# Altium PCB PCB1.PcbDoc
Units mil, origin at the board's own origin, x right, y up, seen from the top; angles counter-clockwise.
Board outline 2300 x 3730 mil, 2 copper layers (Top Layer, Bottom Layer); 8 components, 16 nets, 83 pads, 4 vias.
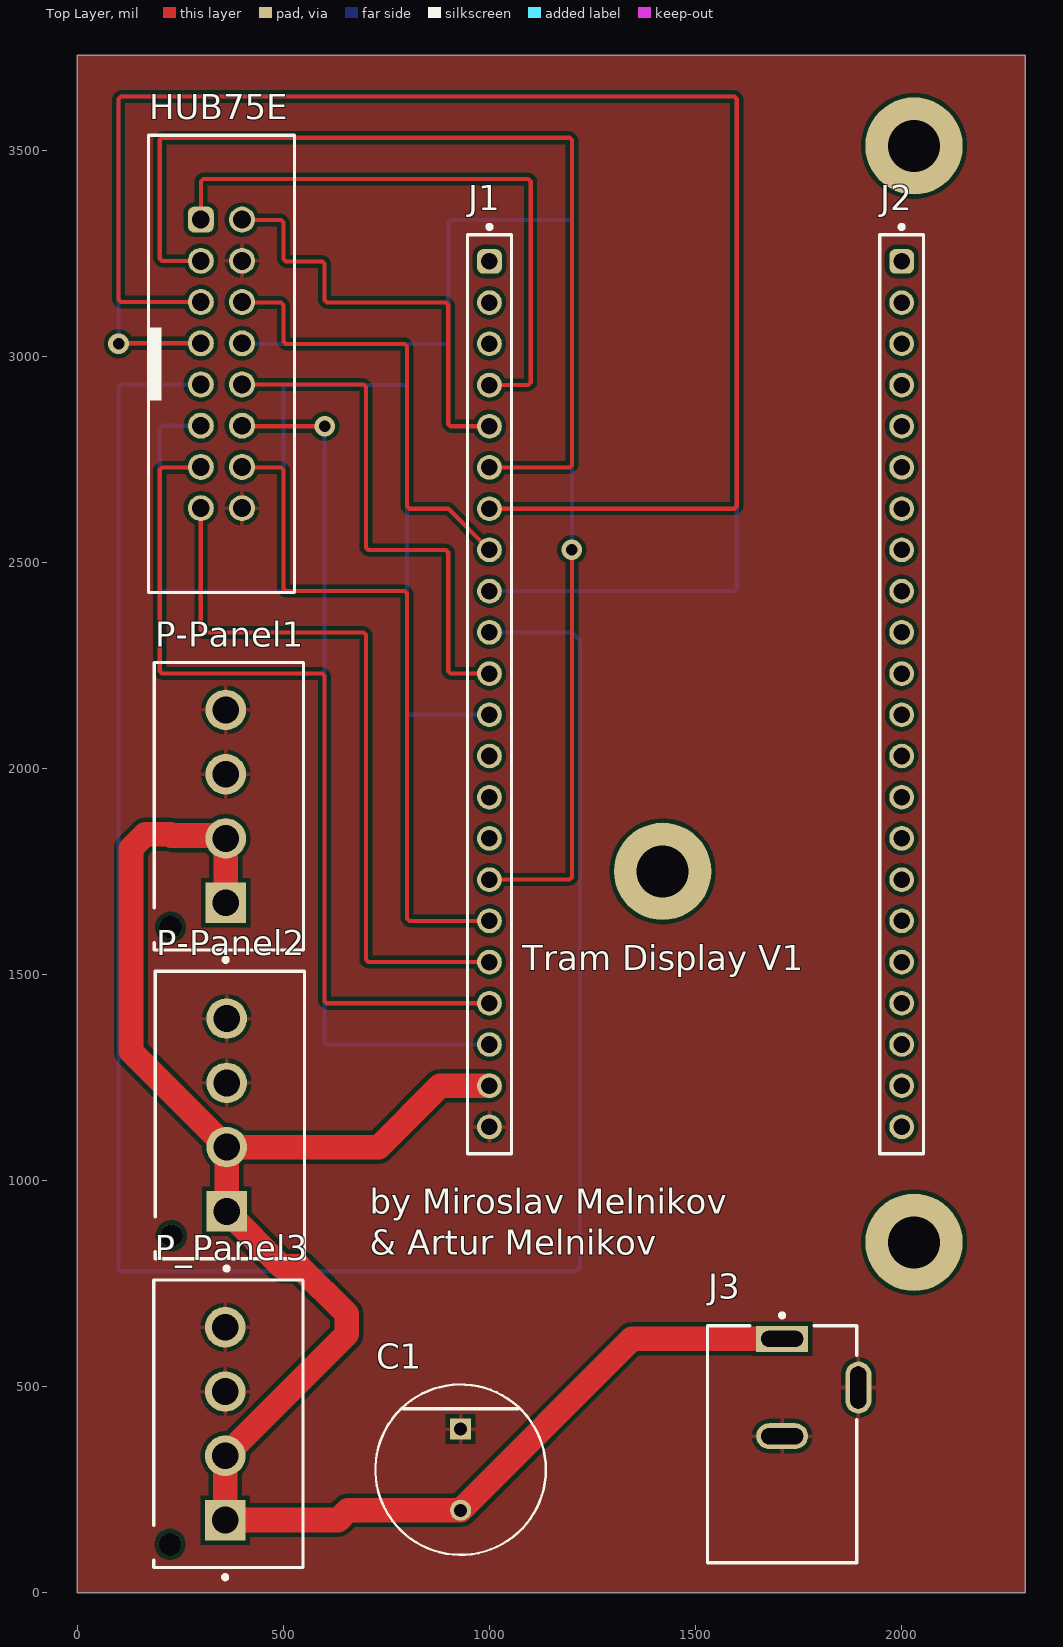
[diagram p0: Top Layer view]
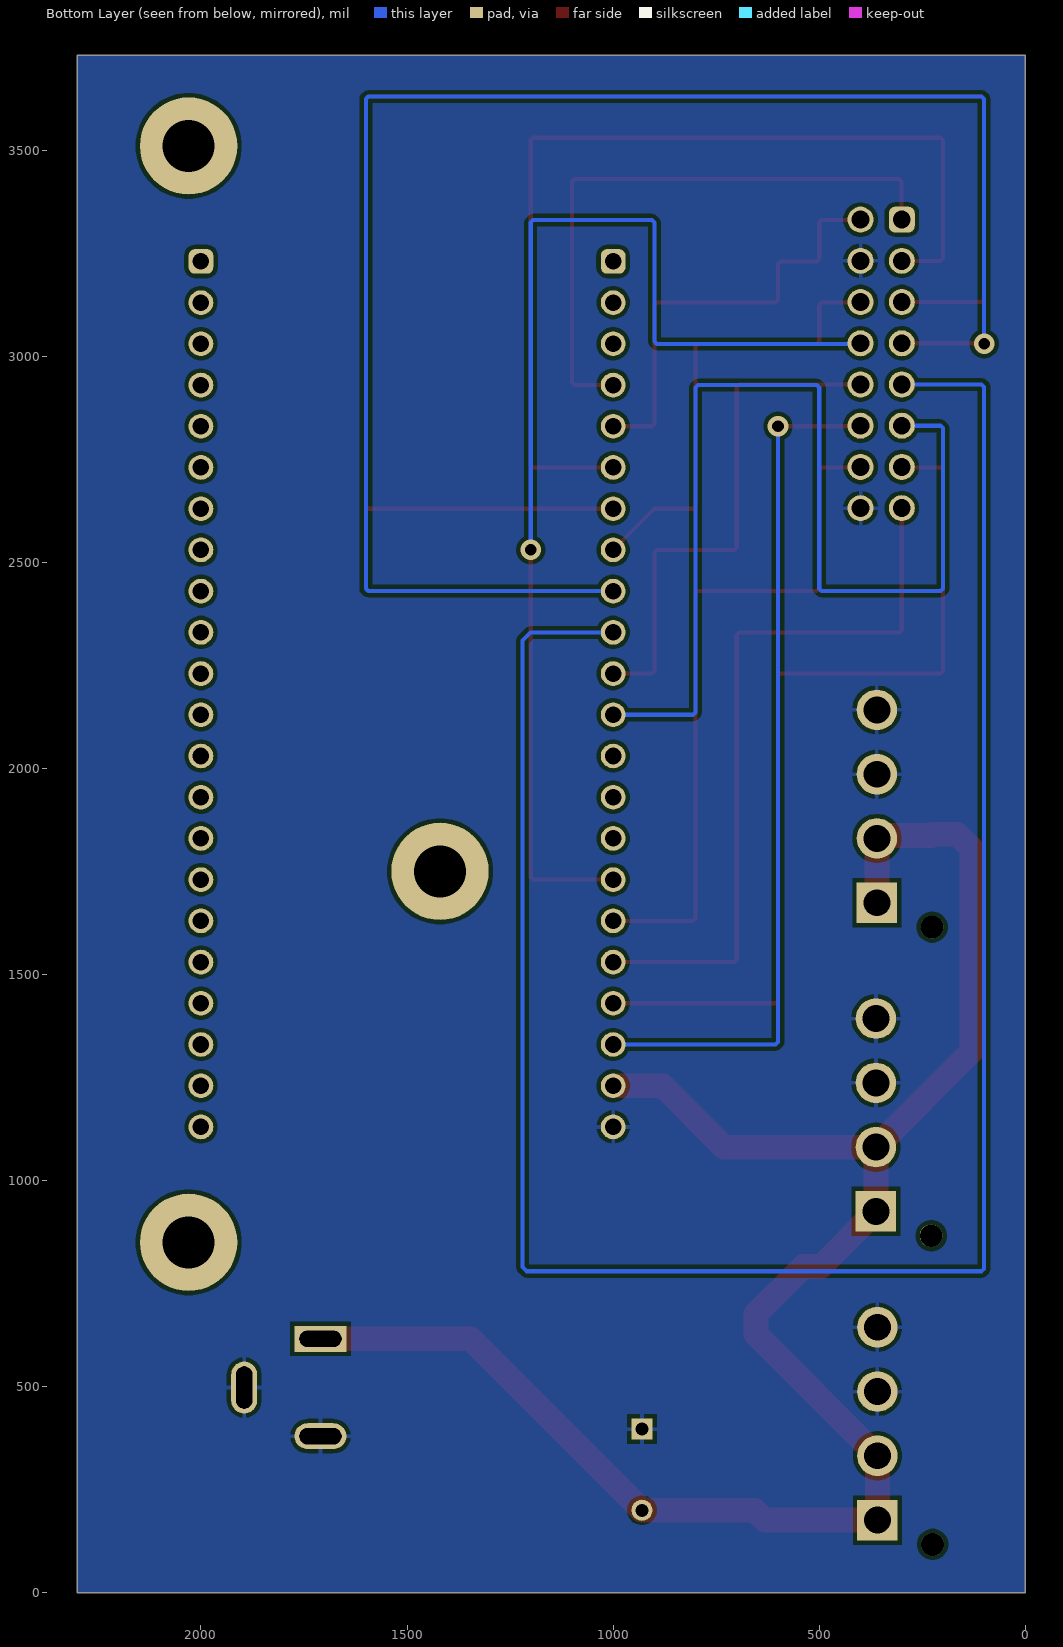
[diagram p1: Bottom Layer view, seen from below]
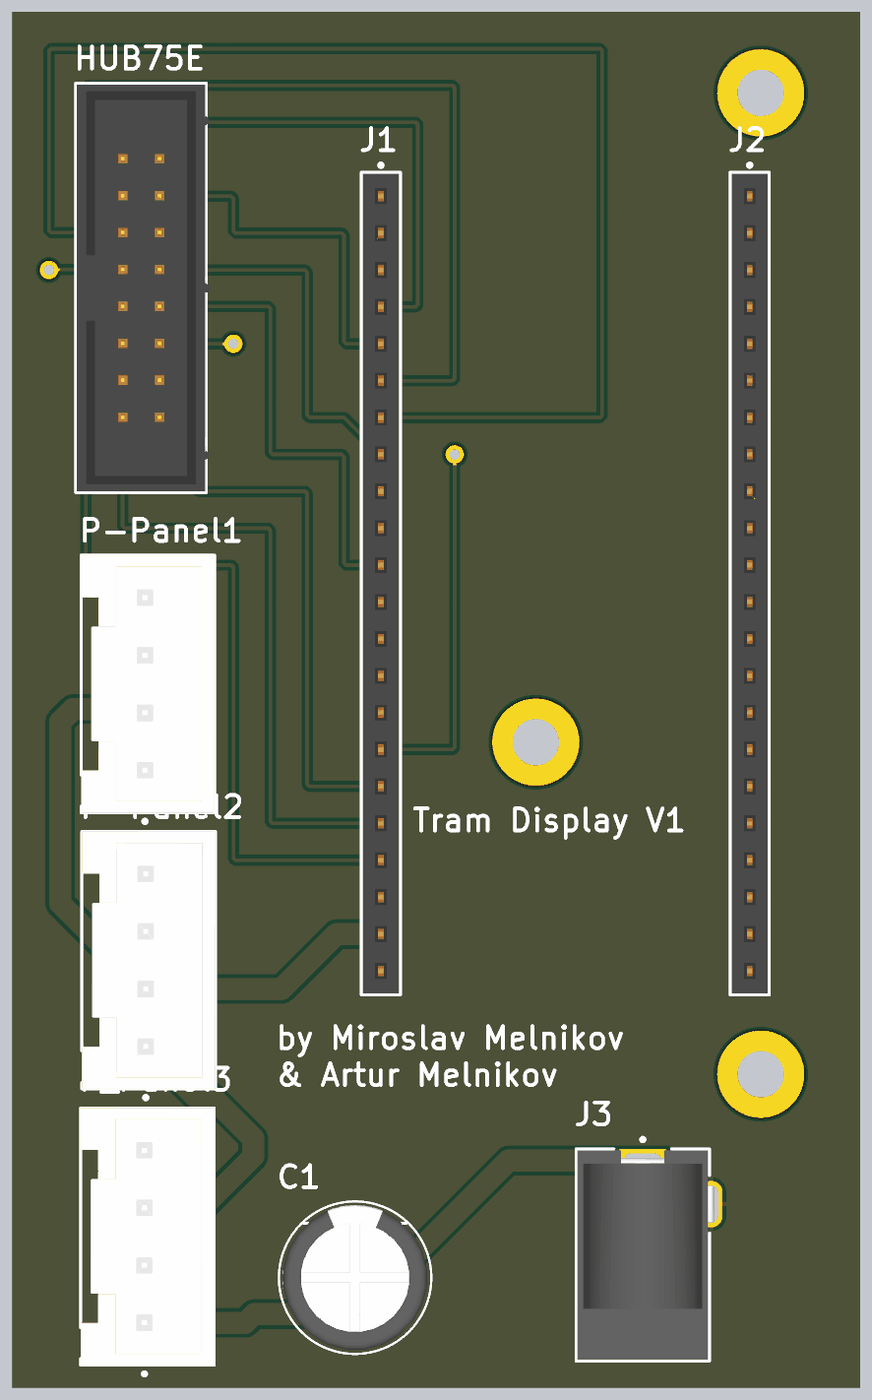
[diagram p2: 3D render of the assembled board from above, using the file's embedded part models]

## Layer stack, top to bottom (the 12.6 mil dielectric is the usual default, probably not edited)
Top Solder: solder mask 0.4, Solder Resist, Dk 3.5
Top Layer: signal copper 1.4
Dielectric 1: dielectric 12.6, FR-4, Dk 4.8
Bottom Layer: signal copper 1.4
Bottom Solder: solder mask 0.4, Solder Resist, Dk 3.5

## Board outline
0,0 2300,0 2300,3730 0,3730

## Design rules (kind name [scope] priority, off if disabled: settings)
AssemblyTestpoint [All] p1: testpointundercomponent=TRUE minsize=40 maxsize=100 preferedsize=60 minholesize=0 maxholesize=40 preferedholesize=32 testpointgrid=1 usegrid=TRUE gridoriginx=900 gridoriginy=1370 gridtolerance=0.01 allowsidetop=TRUE allowsidebottom=TRUE
Clearance [All] p1: gap=10 ignorepadtopadclearanceinfootprint=FALSE
FabricationTestpoint [All] p1: side=3 testpointundercomponent=TRUE minsize=40 maxsize=100 preferedsize=60 minholesize=0 maxholesize=40 preferedholesize=32 testpointgrid=1 allowsidetop=TRUE allowsidebottom=TRUE usegrid=TRUE gridoriginx=900 gridoriginy=1370 gridtolerance=0.01
PolygonConnect [All] p1: connectstyle=Relief reliefconductorwidth=10 reliefentries=4 polygonreliefangle="90 Angle" airgapwidth=10
RoutingVias [All] p1: holewidth=28 width=50 viastyle="Through Hole" minholewidth=28 minwidth=50 maxholewidth=28 maxwidth=50
SolderMaskExpansion [All] p1: expansion=4 istentingtop=FALSE
SupplyNets "Schematic Supply Nets" [InNet('GND')] p1: voltage=0.000
Width Power_Width [InNet('5Vin')] p1: maxlimit=120 minlimit=20 preferedwidth=60 minimp=50.000000 maximp=50.000000 favimp=50.000000
Width [All] p2: maxlimit=10 minlimit=10 preferedwidth=10
28 further rules are at their usual default settings.

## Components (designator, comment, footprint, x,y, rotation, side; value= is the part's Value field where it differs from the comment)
C1 "EEUTA1A102" FP-RAD-TH-D_10_0_5-L_20_2-MFG 930,298.43 r270 top
HUB75E "61201621621" 61201621621 349.63,2981.34 r270 top
J1 "61302211821" 61302211821 1000,2180 r270 top
J2 "61302211821" 61302211821 2000,2180 r270 top
J3 "PJ-102A" FP-PJ-102A-MFG 1710,360 r180 top
P-Panel1 "BH4P-VH-1(LF)(SN)" FP-BH4P-VH-1_LF_SN-MFG 367.87,1907.95 r90 top
P-Panel2 "BH4P-VH-1(LF)(SN)" FP-BH4P-VH-1_LF_SN-MFG 370.19,1158.98 r90 top
P_Panel3 "BH4P-VH-1(LF)(SN)" FP-BH4P-VH-1_LF_SN-MFG 366.63,410 r90 top

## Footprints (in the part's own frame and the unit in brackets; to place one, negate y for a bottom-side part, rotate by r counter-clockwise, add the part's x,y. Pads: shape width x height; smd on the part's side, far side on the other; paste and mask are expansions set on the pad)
61201621621 [mm] "16 pins, straight, gold plating"
  rrect50% 1.6x1.6 hole 1.1: 1(-8.89,-1.27)
  round 1.6 hole 1.1: 2(-8.89,1.27) 3(-6.35,-1.27) 4(-6.35,1.27) 5(-3.81,-1.27) 6(-3.81,1.27) 7(-1.27,-1.27) 8(-1.27,1.27) 9(1.27,-1.27) 10(1.27,1.27) 11(3.81,-1.27) 12(3.81,1.27) 13(6.35,-1.27) 14(6.35,1.27) 15(8.89,-1.27) 16(8.89,1.27)
  silkscreen extent -14.09,-4.5 14.09,4.5, body extent -13.99,-4.42 13.99,4.75, height 9.13
61302211821 [mm] "Socket Header, Pitch 2.54 mm, THT, Vertical, single row, 22p"
  rrect50% 1.52x1.52 hole 1.02: 1(-26.67,0)
  round 1.52 hole 1.02: 2(-24.13,0) 3(-21.59,0) 4(-19.05,0) 5(-16.51,0) 6(-13.97,0) 7(-11.43,0) 8(-8.89,0) 9(-6.35,0) 10(-3.81,0) 11(-1.27,0) 12(1.27,0) 13(3.81,0) 14(6.35,0) 15(8.89,0) 16(11.43,0) 17(13.97,0) 18(16.51,0) 19(19.05,0) 20(21.59,0) 21(24.13,0) 22(26.67,0)
  silkscreen extent -28.92,-1.35 28.32,1.35, body extent -28.19,-1.25 28.19,1.25, height 8.55
FP-BH4P-VH-1_LF_SN-MFG [mm]
  rect 2.5x2.5 hole 1.65 paste-2539.97 mask+0: 1(-5.94,0.2)
  round 2.5 hole 1.65 paste-2539.97 mask+0: 2(-1.98,0.2) 3(1.98,0.2) 4(5.94,0.2)
  round 1.4 hole 1.4 unplated paste-2539.97 mask+0: ""(-7.44,3.6)
  silkscreen extent -9.58,-4.6 8.86,4.6, body extent -8.96,-4.7 8.96,4.7, height 0.25
FP-PJ-102A-MFG [mm]
  rect 3.2x1.6 hole 1 slot 2.6 at 0 deg paste-2539.97 mask+0: 1(0,-6.5)
  rrect100% 3.2x1.6 hole 1 slot 2.6 at 0 deg paste-2539.97 mask+0: 2(0,-0.5)
  rrect100% 1.6x3.2 hole 2.6 slot 1 at 0 deg paste-2539.97 mask+0: 3(-4.7,-3.5)
  silkscreen extent -4.6,-8.07 4.6,7.3, body extent -5.6,-7.4 4.7,7.4, height 0.25
FP-RAD-TH-D_10_0_5-L_20_2-MFG [mm]
  rect 1.3x1.3 hole 0.8 paste-2539.97 mask+0: 1(-2.5,0)
  round 1.3 hole 0.8 paste-2539.97 mask+0: 2(2.5,0)
  silkscreen extent -5.25,-5.25 5.25,5.25, body extent -5.35,-5.35 5.35,5.35, height 0.25

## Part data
C1: library part CMP-05427-000150-1, "Aluminum Electrolytic Capacitors (Radial Lead Type) AEC-Q200 Qualified 1000uF ±20% 10V", Capacitance=1mF, Case/Package=Radial, ESR (Equivalent Series Resistance)=57mR, Max Operating Temperature=125°C, Min Operating Temperature=-40°C, Package Quantity=200, Ripple Current=1.1A, Tolerance=20%, Voltage Rating=10V
HUB75E: library part CMP-1502-00009-3, "WR-BHD Straight Male, Box Header, Through Hole, 2 Rows, 16 Contacts, 2.54mm Pitch", Color=Black, Contact Resistance=20mΩ, Current Rating=3A, Flammability Rating="UL94 V-0", Insulation Resistance=1GΩ, Max Operating Temperature=105°C, Min Operating Temperature=-40°C, Operating Supply Voltage=250V
J1 J2: library part CMP-1502-01352-4, "Btb Conn, Rcpt, 22Pos, 1Row, 2.54Mm Rohs Compliant: Yes", Contact Resistance=20mΩ, Current Rating=3A, Operating Supply Voltage=250V
J3: library part CMP-12637-106234071-1, "PJ-102A 2.0 x 6.5 mm, 2.5 A, Horizontal, Through Hole, Tapered Pins, Dc Power Jack Connector", Color=Black, Current Rating=2.5A, Flammability Rating="UL94 V-0", Insulation Resistance=50MΩ, Max Operating Temperature=85°C, Min Operating Temperature=-25°C, Voltage Rating=24V
P-Panel1 P-Panel2 P_Panel3: library part CMP-17439-000652-1, "VH Series 4 Position 3.96 mm Pitch Through Hole Shrouded Header"

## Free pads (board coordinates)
  round 236.22 hole 125.98 unplated: 5(2030,850) 6(2030,3510) 8(1420,1750)

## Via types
v1: diameter 50, hole 28, Top Layer to Bottom Layer, 4 vias

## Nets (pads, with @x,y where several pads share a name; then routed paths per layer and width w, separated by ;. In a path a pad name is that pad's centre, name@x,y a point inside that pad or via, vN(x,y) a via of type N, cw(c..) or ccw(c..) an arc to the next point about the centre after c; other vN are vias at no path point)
5Vin: C1.2 J1.21 J3.1 P-Panel1.1 P-Panel1.2 P-Panel2.1 P-Panel2.2 P_Panel3.1 P_Panel3.2 | length 4630
  Top Layer w60: P-Panel1.1 P-Panel1.2 352.65,1837.35 227.79,1837.35 225.15,1840 165.15,1840 130,1804.85 130,1313.34 P-Panel2.2 ; J1.21 880,1230 731.02,1081.02 P-Panel2.2 ; J3.1 1345.91,615.91 C1.2 656.31,200 632.45,176.14 P_Panel3.1 P_Panel3.2 653.5,626.79 653.5,676.5 538.8,791.2 496.23,791.2 P-Panel2.1 P-Panel2.2
A: HUB75E.9 J1.10 | length 5216.5
  Bottom Layer w10: HUB75E.9 105.86,2931.34 100,2925.48 100,785.86 105.86,780 1210,780 1220,790 1220,2310 1200,2330 J1.10
B: HUB75E.10 J1.11 | length 1288
  Top Layer w10: HUB75E.10 694.14,2931.34 700,2925.48 700,2535.86 705.86,2530 894.14,2530 900,2524.14 900,2235.86 905.86,2230 J1.11
B1: HUB75E.3 J1.6 | length 2384.6
  Top Layer w10: HUB75E.3 205.86,3231.34 200,3237.2 200,3524.14 205.86,3530 1194.14,3530 1200,3524.14 1200,2735.86 1194.14,2730 J1.6
B2: HUB75E.7 J1.9 | length 4089.9
  Top Layer w10: v1(100,3030) 101.34,3031.34 HUB75E.7
  Bottom Layer w10: v1(100,3030) 100,3624.14 105.86,3630 1594.14,3630 1600,3624.14 1600,2435.86 1594.14,2430 J1.9
C: HUB75E.11 J1.12 | length 2580.4
  Bottom Layer w10: HUB75E.11 205.86,2831.34 200,2825.48 200,2435.86 205.86,2430 494.14,2430 500,2435.86 500,2924.14 505.86,2930 794.14,2930 800,2924.14 800,2135.86 805.86,2130 J1.12
CLK: HUB75E.13 J1.19 | length 2186.5
  Top Layer w10: HUB75E.13 298.3,2730 205.86,2730 200,2724.14 200,2235.86 205.86,2230 594.14,2230 600,2224.14 600,1435.86 605.86,1430 J1.19
D: HUB75E.12 J1.20 | length 2097.5
  Top Layer w10: HUB75E.12 400.97,2830 v1(600,2830)
  Bottom Layer w10: v1(600,2830) 600,1335.86 605.86,1330 J1.20
E: HUB75E.8 J1.16 | length 2887.8
  Top Layer w10: HUB75E.8 399.63,3030.37 v1(400,3030) ; J1.16 1194.14,1730 1200,1735.86 v1(1200,2530)
  Bottom Layer w10: v1(400,3030) 894.14,3030 900,3035.86 900,3324.14 905.86,3330 1194.14,3330 1200,3324.14 v1(1200,2530)
G1: HUB75E.2 J1.5 | length 1080.3
  Top Layer w10: HUB75E.2 400.97,3330 494.14,3330 500,3324.14 500,3235.86 505.86,3230 594.14,3230 600,3224.14 600,3135.86 605.86,3130 894.14,3130 900,3124.14 900,2835.86 905.86,2830 J1.5
G2: HUB75E.6 J1.8 | length 1128.6
  Top Layer w10: HUB75E.6 400.97,3130 494.14,3130 500,3124.14 500,3035.86 505.86,3030 794.14,3030 800,3024.14 800,2635.86 805.86,2630 900,2630 J1.8
GND: C1.1 HUB75E.4 HUB75E.16 J1.22 J3.2 J3.3 P-Panel1.3 P-Panel1.4 P-Panel2.3 P-Panel2.4 P_Panel3.3 P_Panel3.4
LAT: HUB75E.14 J1.17 | length 1687.2
  Top Layer w10: HUB75E.14 400.97,2730 494.14,2730 500,2724.14 500,2435.86 505.86,2430 794.14,2430 800,2424.14 800,1635.86 805.86,1630 J1.17
OE: HUB75E.15 J1.18 | length 1791.4
  Top Layer w10: HUB75E.15 299.63,2335.86 305.49,2330 694.14,2330 700,2324.14 700,1535.86 705.86,1530 J1.18
R1: HUB75E.1 J1.4 | length 1488.5
  Top Layer w10: HUB75E.1 300,3331.7 300,3424.14 305.86,3430 1094.14,3430 1100,3424.14 1100,2935.86 1094.14,2930 J1.4
R2: HUB75E.5 J1.7 | length 3784.6
  Top Layer w10: HUB75E.5 105.86,3131.34 100,3137.2 100,3624.14 105.86,3630 1594.14,3630 1600,3624.14 1600,2635.86 1594.14,2630 J1.7
pads on no net: J1.1 J1.2 J1.3 J1.13 J1.14 J1.15 J2.1 J2.2 J2.3 J2.4 J2.5 J2.6 J2.7 J2.8 J2.9 J2.10 J2.11 J2.12 J2.13 J2.14 J2.15 J2.16 J2.17 J2.18 J2.19 J2.20 J2.21 J2.22 P-Panel1. P-Panel2. P_Panel3.

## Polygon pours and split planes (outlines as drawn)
GND on Bottom Layer "GND_L02_P001" (solid, pour order 1): 2300,0 0,0 0,3730 2300,3730
GND on Top Layer "GND_L01_P000" (solid, pour order 0): 2300,0 0,0 0,3730 2300,3730

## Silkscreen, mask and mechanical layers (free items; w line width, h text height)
Top Overlay:
  text "Tram Display V1" at 1080,1509.99 h60
  text "by Miroslav Melnikov" at 710,919.99 h60
  text "& Artur Melnikov" at 710,820 h60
